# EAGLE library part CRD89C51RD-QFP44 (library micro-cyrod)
CRD89C51RD series 8 - bit single chip micro controller unit (MCU) with 64KB flash & 1K byte RAM embedded. Auto generated by make-symbol-device-package-bsdl.ulp Rev. 35 Source: CRD89C51RD_v001.pdf
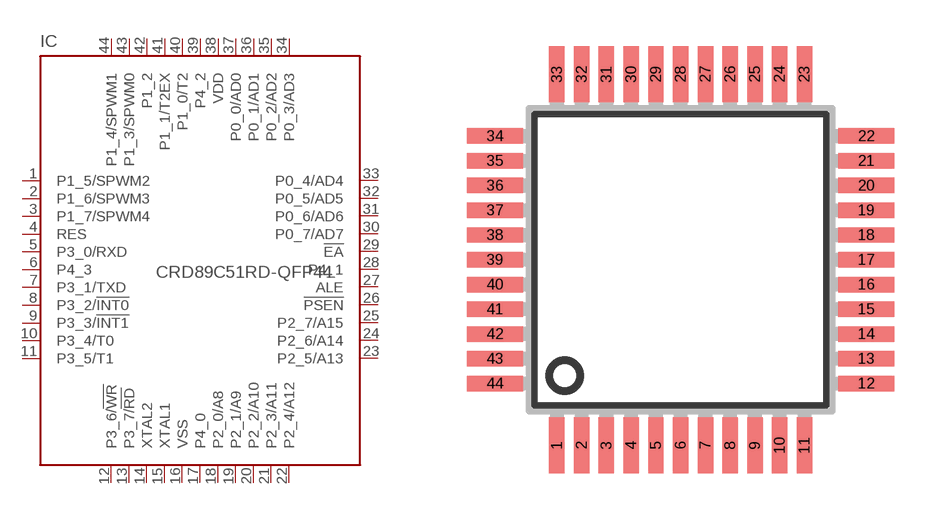
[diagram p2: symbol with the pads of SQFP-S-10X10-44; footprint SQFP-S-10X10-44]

Designator prefix IC

## CRD89C51RD-QFP44 (OC_FARNELL: unknown; OC_NEWARK: unknown)  [SQFP-S-10X10-44]
1  P1_5/SPWM2
2  P1_6/SPWM3
3  P1_7/SPWM4
4  RES  in
5  P3_0/RXD
6  P4_3
7  P3_1/TXD
8  P3_2/!INT0
9  P3_3/!INT1
10  P3_4/T0
11  P3_5/T1
12  P3_6/!WR
13  P3_7/!RD
14  XTAL2  out
15  XTAL1  in
16  VSS  pwr
17  P4_0
18  P2_0/A8
19  P2_1/A9
20  P2_2/A10
21  P2_3/A11
22  P2_4/A12
23  P2_5/A13
24  P2_6/A14
25  P2_7/A15
26  !PSEN  out
27  ALE  out
28  P4_1
29  !EA  in
30  P0_7/AD7
31  P0_6/AD6
32  P0_5/AD5
33  P0_4/AD4
34  P0_3/AD3
35  P0_2/AD2
36  P0_1/AD1
37  P0_0/AD0
38  VDD  pwr
39  P4_2
40  P1_0/T2
41  P1_1/T2EX
42  P1_2
43  P1_3/SPWM0
44  P1_4/SPWM1

## Footprint SQFP-S-10X10-44 (pad centres in mm)
QFP44 shrink quad flat pack, square
smd 0.5 x 1.8: 1 -4,-6; 2 -3.2,-6; 3 -2.4,-6; 4 -1.6,-6; 5 -0.8,-6; 6 0,-6; 7 0.8,-6; 8 1.6,-6; 9 2.4,-6; 10 3.2,-6; 11 4,-6; 23 4,6; 24 3.2,6; 25 2.4,6; 26 1.6,6; 27 0.8,6; 28 0,6; 29 -0.8,6; 30 -1.6,6; 31 -2.4,6; 32 -3.2,6; 33 -4,6
smd 1.8 x 0.5: 12 6,-4; 13 6,-3.2; 14 6,-2.4; 15 6,-1.6; 16 6,-0.8; 17 6,0; 18 6,0.8; 19 6,1.6; 20 6,2.4; 21 6,3.2; 22 6,4; 34 -6,4; 35 -6,3.2; 36 -6,2.4; 37 -6,1.6; 38 -6,0.8; 39 -6,0; 40 -6,-0.8; 41 -6,-1.6; 42 -6,-2.4; 43 -6,-3.2; 44 -6,-4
